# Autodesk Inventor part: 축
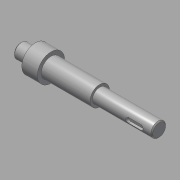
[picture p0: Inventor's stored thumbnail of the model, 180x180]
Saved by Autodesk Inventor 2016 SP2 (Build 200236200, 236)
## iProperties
Created: 2015-09
Part Number: 축
Material: 강철, 연강
Document SubType Name: Modeling
Designer: mduedu
Density: 7.86 g/cm^3
Mass: 263.424 g
Surface Area: 86.4309 cm^2
Volume: 33.5145 cm^3
Appearance: 강철
Author: mduedu
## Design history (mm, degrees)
sketch "스케치1"
  geometry: L1 (-71, 0)-(71, 0); L2 (-71, 0)-(-71, 7.5); L3 (-71, 7.5)-(-56, 7.5); L4 (-56, 7.5)-(-56, 14); L5 (-56, 14)-(-40, 14); L6 (-40, 14)-(-40, 10); L7 (-40, 10)-(10, 10); L8 (10, 10)-(10, 7.5); L9 (10, 7.5)-(71, 7.5); L10 (71, 7.5)-(71, 0); 2 further points
  constraints: 20 end point, 5 parallel, 2 horizontal, 2 perpendicular, 1 coincident, 1 midpoint, 1 vertical
  dimensions: "d0" = 142 distance of L1.start L1.end; "d2" = 16 distance of L4.end L5.end; "d3" = 50 distance of L6.end L7.end; "d5" = 15 diameter of L3 L1; "d6" = 15 diameter of L9 L1; "d7" = 20 diameter of L7 L1; "d8" = 28 diameter of L5 L1; "d31" = 15 distance of L2.end L3.end
revolve "회전1" sketch "스케치1" stored, may be unused: angle "d9" = 90 deg
node "작업 평면1"
sketch "스케치2"
  geometry: L1 (6, 2.5)-(19, 2.5); L2 (19, -2.5)-(6, -2.5); L3 (6, 2.5)-(19, -2.5); L4 (19, 2.5)-(6, -2.5); L5 (30.5, -7.5)-(30.5, 7.5) reference; A1 r 2.5 centre (6, 0) between (6, 2.5) and (6, -2.5); A2 r 2.5 centre (19, 0) between (19, -2.5) and (19, 2.5); 2 further points
  constraints: 8 end point, 4 point on circle, 4 tangent, 2 centre point, 2 midpoint, 1 horizontal, 1 horizontal alignment, 1 parallel
  dimensions: "d10" = 18 dimension on A2 A1; "d12" = 9 distance edge to line of A2 L5; "d13" = 5 distance between parallel lines of L2 L1
extrude "돌출1" cut sketch "스케치2" distance "d14" = 3; taper "d15" = 0 deg
node "작업 평면2"
sketch "스케치4"
  geometry: L1 (3, -3)-(-13, -3); L2 (-13, 3)-(3, 3); L3 (-25, 10)-(-25, -10) reference; A1 r 3 centre (-13, 0) between (-13, 3) and (-13, -3); A2 r 3 centre (3, 0) between (3, -3) and (3, 3); 1 further point
  constraints: 4 end point, 4 point on circle, 4 tangent, 2 centre point, 1 horizontal, 1 horizontal alignment, 1 parallel
  dimensions: "d16" = 22 dimension on A1 A2; "d18" = 6 distance between parallel lines of L2 L1; "d19" = 9 distance edge to line of A1 L3
extrude "돌출2" cut sketch "스케치4" distance "d20" = 3.5; taper "d21" = 0 deg
sketch "스케치5"
  geometry: L1 (10, 7.5)-(71, 7.5) reference; L2 (10, -7.5)-(71, -7.5) reference; L3 (45, 7.5)-(45, -7.5); L4 (45, -5.5)-(43, -7.5); L5 (45, -7.5)-(43, -7.5); L6 (45, -7.5)-(45, -5.5); L7 (10, -10)-(10, 10) reference; 1 further point
  constraints: 8 end point, 4 point on line, 1 collinear, 1 perpendicular
  dimensions: "d22" = 4 diameter of L4.end L3; "d24" = 45 deg angle of L3 L4; "d26" = 35 distance between parallel lines of L3 L7
revolve "회전2" sketch "스케치5" stored, may be unused: angle "d27" = 90 deg
chamfer "모따기1" distance "d28" = 1; stored, may be unused: second distance "d29" = 2, angle "d30" = 45 deg
sketch "스케치6"
  geometry: L1 (45, -5.5)-(43, -7.5) reference; L2 (45, -5.5)-(47, -7.5) reference; 2 further points
  constraints: 1 coincident
node "솔리드1"
